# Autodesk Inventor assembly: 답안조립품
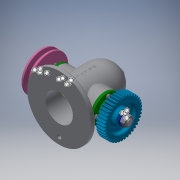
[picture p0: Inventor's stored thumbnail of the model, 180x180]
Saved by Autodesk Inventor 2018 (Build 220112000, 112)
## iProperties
Created: 2019-11
Part Number: 답안조립품
Document SubType Name: Assembly
Designer: Administrator
Author: Administrator
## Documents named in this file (14)
- C:\Users\Administrator\Desktop\491104V1060\답안조립품.iam
- C:\Users\Administrator\Desktop\491104V1060\본체.ipt
- C:\Users\Administrator\Desktop\491104V1060\축.ipt
- C:\Users\Administrator\Desktop\491104V1060\베어링 6203.ipt
- C:\Users\Administrator\Desktop\491104V1060\부시.ipt
- C:\Users\Administrator\Desktop\491104V1060\커버.ipt
- C:\Users\Administrator\Desktop\491104V1060\오일 실 26 38 8.ipt
- C:\Users\Administrator\Desktop\491104V1060\키 5x5x12.ipt
- C:\Users\Administrator\Desktop\491104V1060\V-벨트풀리.ipt
- V-벨트풀리.ipt
- C:\Users\Administrator\Desktop\491104V1060\스퍼기어.ipt
- C:\Users\Administrator\Desktop\491104V1060\와셔 12x24.ipt
- C:\Users\Administrator\Desktop\491104V1060\너트 M12x1.25.ipt
- C:\Users\Administrator\Desktop\491104V1060\볼트 M4.ipt
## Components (1 placed, 1 different names)
1. V-벨트풀리:1
